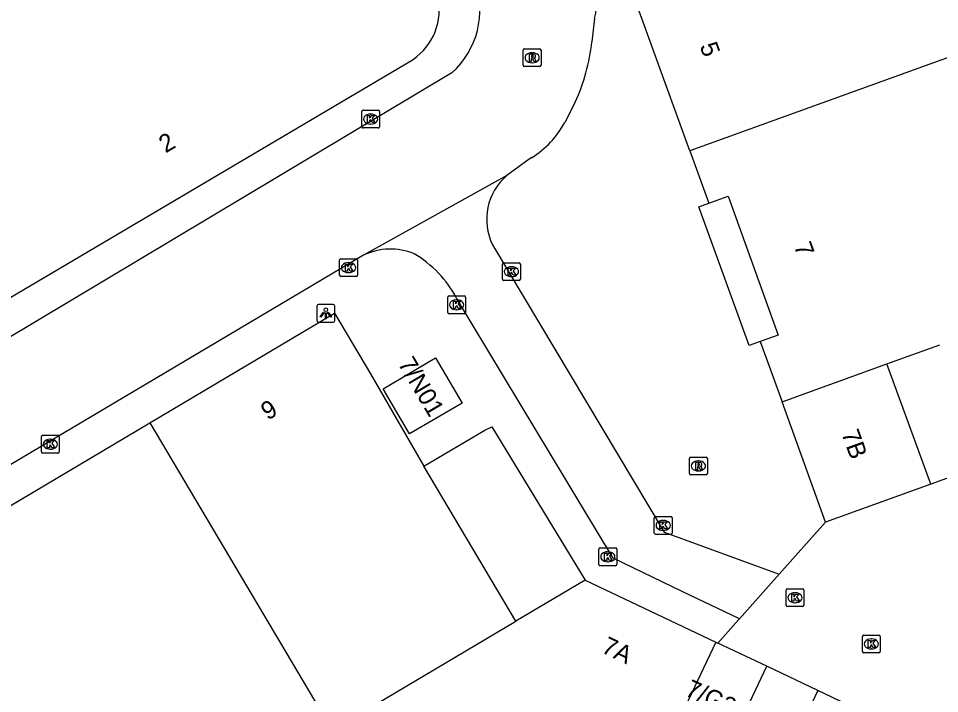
# Model space of a CAD drawing. Extents: x 159503 to 160347, y 382525 to 383272.
# Drawn here: x 159699.9 to 159751.6, y 383023.8 to 383061.7 of the extents above; entities that cross this region are included whole.
import ezdxf

# ---------------------------------------------------------------- set-up
doc = ezdxf.new("R2010")
doc.units = 0
for name, color, linetype in [('IMGEO_Kolk', 7, 'Continuous'), ('IMGEO_Lichtpunt', 7, 'Continuous'), ('IMGEO_Pand', 7, 'Continuous'), ('IMGEO_Pand_nummerreeks', 7, 'Continuous'), ('IMGEO_Rijbaan_lokaal_open', 7, 'Continuous'), ('IMGEO_Rioolput', 7, 'Continuous'), ('IMGEO_Voetpad_open', 7, 'Continuous')]:
    doc.layers.add(name, color=color, linetype=linetype)

msp = doc.modelspace()

# ---------------------------------------------------------------- linework, layer by layer
at = {"layer": 'IMGEO_Kolk'}
for p, q in [((159719.135, 383055.643), (159719.135, 383056.495)), ((159719.21, 383056.569), (159720.062, 383056.569)), ((159720.136, 383056.495), (159720.136, 383055.643)), ((159719.623, 383056.349), (159719.648, 383056.349)), ((159720.062, 383055.569), (159719.21, 383055.569)), ((159719.646, 383055.789), (159719.621, 383055.789)), ((159717.898, 383047.304), (159717.898, 383048.156)), ((159717.973, 383048.23), (159718.825, 383048.23)), ((159718.899, 383048.156), (159718.899, 383047.304)), ((159718.386, 383048.01), (159718.411, 383048.01)), ((159727.046, 383047.074), (159727.046, 383047.926)), ((159727.121, 383048), (159727.973, 383048)), ((159727.534, 383047.78), (159727.559, 383047.78)), ((159728.047, 383047.926), (159728.047, 383047.074)), ((159718.825, 383047.23), (159717.973, 383047.23)), ((159718.409, 383047.45), (159718.384, 383047.45)), ((159727.557, 383047.22), (159727.532, 383047.22)), ((159727.973, 383047), (159727.121, 383047)), ((159723.969, 383045.212), (159723.969, 383046.064)), ((159724.044, 383046.138), (159724.896, 383046.138)), ((159724.97, 383046.064), (159724.97, 383045.212)), ((159724.457, 383045.918), (159724.482, 383045.918)), ((159724.896, 383045.138), (159724.044, 383045.138)), ((159724.48, 383045.358), (159724.455, 383045.358)), ((159701.226, 383038.312), (159702.078, 383038.312)), ((159701.151, 383037.386), (159701.151, 383038.238)), ((159701.639, 383038.092), (159701.664, 383038.092)), ((159702.152, 383038.238), (159702.152, 383037.386)), ((159702.078, 383037.312), (159701.226, 383037.312)), ((159701.662, 383037.532), (159701.637, 383037.532)), ((159735.567, 383032.824), (159735.567, 383033.676)), ((159735.642, 383033.75), (159736.494, 383033.75)), ((159736.568, 383033.676), (159736.568, 383032.824)), ((159736.055, 383033.53), (159736.08, 383033.53)), ((159736.494, 383032.75), (159735.642, 383032.75)), ((159736.078, 383032.97), (159736.053, 383032.97)), ((159732.458, 383031.062), (159732.458, 383031.914)), ((159732.533, 383031.988), (159733.385, 383031.988)), ((159732.946, 383031.768), (159732.971, 383031.768)), ((159733.459, 383031.914), (159733.459, 383031.062)), ((159732.969, 383031.208), (159732.944, 383031.208)), ((159733.385, 383030.988), (159732.533, 383030.988)), ((159742.969, 383028.766), (159742.969, 383029.618)), ((159743.044, 383029.692), (159743.896, 383029.692)), ((159743.457, 383029.472), (159743.482, 383029.472)), ((159743.97, 383029.618), (159743.97, 383028.766)), ((159743.896, 383028.692), (159743.044, 383028.692)), ((159743.48, 383028.912), (159743.455, 383028.912)), ((159747.257, 383026.17), (159747.257, 383027.022)), ((159747.332, 383027.096), (159748.184, 383027.096)), ((159747.745, 383026.876), (159747.77, 383026.876)), ((159748.258, 383027.022), (159748.258, 383026.17)), ((159748.184, 383026.096), (159747.332, 383026.096)), ((159747.768, 383026.316), (159747.743, 383026.316))]:
    msp.add_line(p, q, dxfattribs=at)
for points in [[(159719.135, 383055.643), (159719.135, 383056.495)], [(159719.21, 383056.569), (159720.062, 383056.569)], [(159720.136, 383056.495), (159720.136, 383055.643)], [(159719.456, 383056.269), (159719.579, 383056.269), (159719.579, 383056.118), (159719.709, 383056.269), (159719.873, 383056.269), (159719.727, 383056.118), (159719.88, 383055.869), (159719.728, 383055.869), (159719.643, 383056.033), (159719.579, 383055.966), (159719.579, 383055.869), (159719.456, 383055.869), (159719.456, 383056.269)], [(159720.062, 383055.569), (159719.21, 383055.569)], [(159717.898, 383047.304), (159717.898, 383048.156)], [(159717.973, 383048.23), (159718.825, 383048.23)], [(159718.899, 383048.156), (159718.899, 383047.304)], [(159718.219, 383047.93), (159718.342, 383047.93), (159718.342, 383047.779), (159718.472, 383047.93), (159718.636, 383047.93), (159718.49, 383047.779), (159718.643, 383047.53), (159718.491, 383047.53), (159718.406, 383047.694), (159718.342, 383047.627), (159718.342, 383047.53), (159718.219, 383047.53), (159718.219, 383047.93)], [(159727.046, 383047.074), (159727.046, 383047.926)], [(159727.121, 383048), (159727.973, 383048)], [(159727.367, 383047.7), (159727.49, 383047.7), (159727.49, 383047.549), (159727.62, 383047.7), (159727.784, 383047.7), (159727.638, 383047.549), (159727.791, 383047.3), (159727.639, 383047.3), (159727.554, 383047.464), (159727.49, 383047.397), (159727.49, 383047.3), (159727.367, 383047.3), (159727.367, 383047.7)], [(159728.047, 383047.926), (159728.047, 383047.074)], [(159718.825, 383047.23), (159717.973, 383047.23)], [(159727.973, 383047), (159727.121, 383047)], [(159723.969, 383045.212), (159723.969, 383046.064)], [(159724.044, 383046.138), (159724.896, 383046.138)], [(159724.97, 383046.064), (159724.97, 383045.212)], [(159724.29, 383045.838), (159724.413, 383045.838), (159724.413, 383045.687), (159724.543, 383045.838), (159724.707, 383045.838), (159724.561, 383045.687), (159724.714, 383045.438), (159724.562, 383045.438), (159724.477, 383045.602), (159724.413, 383045.535), (159724.413, 383045.438), (159724.29, 383045.438), (159724.29, 383045.838)], [(159724.896, 383045.138), (159724.044, 383045.138)], [(159701.226, 383038.312), (159702.078, 383038.312)], [(159701.151, 383037.386), (159701.151, 383038.238)], [(159701.472, 383038.012), (159701.595, 383038.012), (159701.595, 383037.861), (159701.725, 383038.012), (159701.889, 383038.012), (159701.743, 383037.861), (159701.896, 383037.612), (159701.744, 383037.612), (159701.659, 383037.776), (159701.595, 383037.709), (159701.595, 383037.612), (159701.472, 383037.612), (159701.472, 383038.012)], [(159702.152, 383038.238), (159702.152, 383037.386)], [(159702.078, 383037.312), (159701.226, 383037.312)], [(159735.567, 383032.824), (159735.567, 383033.676)], [(159735.642, 383033.75), (159736.494, 383033.75)], [(159736.568, 383033.676), (159736.568, 383032.824)], [(159735.888, 383033.45), (159736.011, 383033.45), (159736.011, 383033.299), (159736.141, 383033.45), (159736.305, 383033.45), (159736.159, 383033.299), (159736.312, 383033.05), (159736.16, 383033.05), (159736.075, 383033.214), (159736.011, 383033.147), (159736.011, 383033.05), (159735.888, 383033.05), (159735.888, 383033.45)], [(159736.494, 383032.75), (159735.642, 383032.75)], [(159732.458, 383031.062), (159732.458, 383031.914)], [(159732.533, 383031.988), (159733.385, 383031.988)], [(159732.779, 383031.688), (159732.902, 383031.688), (159732.902, 383031.537), (159733.032, 383031.688), (159733.196, 383031.688), (159733.05, 383031.537), (159733.203, 383031.288), (159733.051, 383031.288), (159732.966, 383031.452), (159732.902, 383031.385), (159732.902, 383031.288), (159732.779, 383031.288), (159732.779, 383031.688)], [(159733.459, 383031.914), (159733.459, 383031.062)], [(159733.385, 383030.988), (159732.533, 383030.988)], [(159742.969, 383028.766), (159742.969, 383029.618)], [(159743.044, 383029.692), (159743.896, 383029.692)], [(159743.97, 383029.618), (159743.97, 383028.766)], [(159743.29, 383029.392), (159743.413, 383029.392), (159743.413, 383029.241), (159743.543, 383029.392), (159743.707, 383029.392), (159743.561, 383029.241), (159743.714, 383028.992), (159743.562, 383028.992), (159743.477, 383029.156), (159743.413, 383029.089), (159743.413, 383028.992), (159743.29, 383028.992), (159743.29, 383029.392)], [(159743.896, 383028.692), (159743.044, 383028.692)], [(159747.257, 383026.17), (159747.257, 383027.022)], [(159747.332, 383027.096), (159748.184, 383027.096)], [(159748.258, 383027.022), (159748.258, 383026.17)], [(159747.578, 383026.796), (159747.701, 383026.796), (159747.701, 383026.645), (159747.831, 383026.796), (159747.995, 383026.796), (159747.849, 383026.645), (159748.002, 383026.396), (159747.85, 383026.396), (159747.765, 383026.56), (159747.701, 383026.493), (159747.701, 383026.396), (159747.578, 383026.396), (159747.578, 383026.796)], [(159748.184, 383026.096), (159747.332, 383026.096)]]:
    msp.add_lwpolyline(points, dxfattribs=at)
for centre, start, end in [((159719.212, 383056.493), 91.552, 178.448), ((159719.212, 383056.493), 91.552, 178.448), ((159720.06, 383056.493), 1.552, 88.448), ((159720.06, 383056.493), 1.552, 88.448), ((159719.212, 383055.645), 181.552, 268.448), ((159719.212, 383055.645), 181.552, 268.448), ((159720.06, 383055.645), 271.552, 358.448), ((159720.06, 383055.645), 271.552, 358.448), ((159717.975, 383048.154), 91.552, 178.448), ((159717.975, 383048.154), 91.552, 178.448), ((159718.823, 383048.154), 1.552, 88.448), ((159718.823, 383048.154), 1.552, 88.448), ((159727.123, 383047.924), 91.552, 178.448), ((159727.123, 383047.924), 91.552, 178.448), ((159727.971, 383047.924), 1.552, 88.448), ((159727.971, 383047.924), 1.552, 88.448), ((159717.975, 383047.306), 181.552, 268.448), ((159717.975, 383047.306), 181.552, 268.448), ((159718.823, 383047.306), 271.552, 358.448), ((159718.823, 383047.306), 271.552, 358.448), ((159727.123, 383047.076), 181.552, 268.448), ((159727.123, 383047.076), 181.552, 268.448), ((159727.971, 383047.076), 271.552, 358.448), ((159727.971, 383047.076), 271.552, 358.448), ((159724.046, 383046.062), 91.552, 178.448), ((159724.046, 383046.062), 91.552, 178.448), ((159724.894, 383046.062), 1.552, 88.448), ((159724.894, 383046.062), 1.552, 88.448), ((159724.046, 383045.214), 181.552, 268.448), ((159724.046, 383045.214), 181.552, 268.448), ((159724.894, 383045.214), 271.552, 358.448), ((159724.894, 383045.214), 271.552, 358.448), ((159701.228, 383038.236), 91.552, 178.448), ((159701.228, 383038.236), 91.552, 178.448), ((159702.076, 383038.236), 1.552, 88.448), ((159702.076, 383038.236), 1.552, 88.448), ((159701.228, 383037.388), 181.552, 268.448), ((159701.228, 383037.388), 181.552, 268.448), ((159702.076, 383037.388), 271.552, 358.448), ((159702.076, 383037.388), 271.552, 358.448), ((159735.644, 383033.674), 91.552, 178.448), ((159735.644, 383033.674), 91.552, 178.448), ((159736.492, 383033.674), 1.552, 88.448), ((159736.492, 383033.674), 1.552, 88.448), ((159735.644, 383032.826), 181.552, 268.448), ((159735.644, 383032.826), 181.552, 268.448), ((159736.492, 383032.826), 271.552, 358.448), ((159736.492, 383032.826), 271.552, 358.448), ((159732.535, 383031.912), 91.552, 178.448), ((159732.535, 383031.912), 91.552, 178.448), ((159733.383, 383031.912), 1.552, 88.448), ((159733.383, 383031.912), 1.552, 88.448), ((159732.535, 383031.064), 181.552, 268.448), ((159732.535, 383031.064), 181.552, 268.448), ((159733.383, 383031.064), 271.552, 358.448), ((159733.383, 383031.064), 271.552, 358.448), ((159743.046, 383029.616), 91.552, 178.448), ((159743.046, 383029.616), 91.552, 178.448), ((159743.894, 383029.616), 1.552, 88.448), ((159743.894, 383029.616), 1.552, 88.448), ((159743.046, 383028.768), 181.552, 268.448), ((159743.046, 383028.768), 181.552, 268.448), ((159743.894, 383028.768), 271.552, 358.448), ((159743.894, 383028.768), 271.552, 358.448), ((159747.334, 383027.02), 91.552, 178.448), ((159747.334, 383027.02), 91.552, 178.448), ((159748.182, 383027.02), 1.552, 88.448), ((159748.182, 383027.02), 1.552, 88.448), ((159747.334, 383026.172), 181.552, 268.448), ((159747.334, 383026.172), 181.552, 268.448), ((159748.182, 383026.172), 271.552, 358.448), ((159748.182, 383026.172), 271.552, 358.448)]:
    msp.add_arc(centre, 0.0765, start, end, dxfattribs=at)
for centre, major_axis, ratio, start_param, end_param in [((159719.622, 383056.069), (-0.387, 0.002), 0.722429, 4.712389, 7.853982), ((159719.647, 383056.069), (-0.39, 0.002), 0.717154, 1.570796, 4.712389), ((159718.385, 383047.73), (-0.387, 0.002), 0.722429, 4.712389, 7.853982), ((159718.41, 383047.73), (-0.39, 0.002), 0.717154, 1.570796, 4.712389), ((159727.533, 383047.5), (-0.387, 0.002), 0.722429, 4.712389, 7.853982), ((159727.558, 383047.5), (-0.39, 0.002), 0.717154, 1.570796, 4.712389), ((159724.456, 383045.638), (-0.387, 0.002), 0.722429, 4.712389, 7.853982), ((159724.481, 383045.638), (-0.39, 0.002), 0.717154, 1.570796, 4.712389), ((159701.638, 383037.812), (-0.387, 0.002), 0.722429, 4.712389, 7.853982), ((159701.663, 383037.812), (-0.39, 0.002), 0.717154, 1.570796, 4.712389), ((159736.054, 383033.25), (-0.387, 0.002), 0.722429, 4.712389, 7.853982), ((159736.079, 383033.25), (-0.39, 0.002), 0.717154, 1.570796, 4.712389), ((159732.945, 383031.488), (-0.387, 0.002), 0.722429, 4.712389, 7.853982), ((159732.97, 383031.488), (-0.39, 0.002), 0.717154, 1.570796, 4.712389), ((159743.456, 383029.192), (-0.387, 0.002), 0.722429, 4.712389, 7.853982), ((159743.481, 383029.192), (-0.39, 0.002), 0.717154, 1.570796, 4.712389), ((159747.744, 383026.596), (-0.387, 0.002), 0.722429, 4.712389, 7.853982), ((159747.769, 383026.596), (-0.39, 0.002), 0.717154, 1.570796, 4.712389)]:
    msp.add_ellipse(centre, major_axis=major_axis, ratio=ratio, start_param=start_param, end_param=end_param, dxfattribs=at)
at = {"layer": 'IMGEO_Lichtpunt'}
for p, q in [((159716.625, 383045.564), (159716.625, 383044.757)), ((159716.625, 383045.564), (159716.625, 383044.757)), ((159717.527, 383045.659), (159716.719, 383045.659)), ((159717.527, 383045.659), (159716.719, 383045.659)), ((159717.621, 383044.757), (159717.621, 383045.564)), ((159717.621, 383044.757), (159717.621, 383045.564)), ((159716.719, 383044.663), (159717.527, 383044.663)), ((159716.719, 383044.663), (159717.527, 383044.663))]:
    msp.add_line(p, q, dxfattribs=at)
for points in [[(159716.999, 383045.228), (159717.038, 383045.2), (159716.85, 383044.938), (159716.812, 383044.965), (159716.999, 383045.228)], [(159717.101, 383045.18), (159717.148, 383045.18), (159717.148, 383044.858), (159717.101, 383044.858), (159717.101, 383045.18)], [(159717.211, 383045.2), (159717.249, 383045.227), (159717.436, 383044.965), (159717.397, 383044.937), (159717.211, 383045.2)]]:
    msp.add_lwpolyline(points, dxfattribs=at)
msp.add_circle((159717.124, 383045.362), 0.0994, dxfattribs=at)
for centre, start, end in [((159716.719, 383045.564), 90, 180), ((159716.719, 383045.564), 90, 180), ((159717.527, 383045.564), 0, 90), ((159717.527, 383045.564), 0, 90), ((159716.719, 383044.757), 180, 270), ((159716.719, 383044.757), 180, 270), ((159717.527, 383044.757), 270, 0), ((159717.527, 383044.757), 270, 360)]:
    msp.add_arc(centre, 0.0946, start, end, dxfattribs=at)
at = {"layer": 'IMGEO_Pand'}
for points in [[(159737.559, 383054.283), (159734.103, 383063.845)], [(159763.853, 383063.79), (159737.559, 383054.283)], [(159697.266, 383044.792), (159722.024, 383059.424)], [(159737.559, 383054.283), (159738.623, 383051.341)], [(159738.623, 383051.341), (159739.709, 383051.733), (159742.526, 383043.943), (159741.521, 383043.58)], [(159707.235, 383039.014), (159717.603, 383045.17), (159719.625, 383041.765), (159722.634, 383036.573)], [(159741.521, 383043.58), (159742.744, 383040.198)], [(159748.633, 383042.324), (159748.835, 383042.397), (159751.595, 383043.394)], [(159723.282, 383042.66), (159724.785, 383040.12), (159721.813, 383038.389), (159720.341, 383040.928), (159723.282, 383042.66)], [(159742.744, 383040.198), (159745.695, 383041.263), (159748.633, 383042.324)], [(159751.091, 383035.561), (159748.633, 383042.324)], [(159745.192, 383033.428), (159742.744, 383040.198)], [(159681.512, 383023.741), (159707.235, 383039.014)], [(159707.235, 383039.014), (159717.447, 383021.814)], [(159727.798, 383027.878), (159722.634, 383036.573)], [(159754.041, 383036.627), (159751.091, 383035.561)], [(159751.091, 383035.561), (159748.141, 383034.494), (159745.192, 383033.428)], [(159731.677, 383030.181), (159727.798, 383027.878)], [(159731.677, 383030.181), (159739.021, 383026.698)], [(159719.37, 383022.877), (159727.798, 383027.878)], [(159739.021, 383026.698), (159736.443, 383021.244)], [(159739.021, 383026.698), (159739.133, 383026.645)], [(159741.889, 383025.338), (159739.133, 383026.645)], [(159739.304, 383019.887), (159741.889, 383025.338)], [(159744.757, 383023.978), (159741.889, 383025.338)], [(159744.757, 383023.978), (159742.172, 383018.527)], [(159747.624, 383022.618), (159744.757, 383023.978)]]:
    msp.add_lwpolyline(points, dxfattribs=at)
msp.add_arc((159720.134, 383062.196), 3.356, 304.2878, 13.0138, dxfattribs=at)
at = {"layer": 'IMGEO_Rijbaan_lokaal_open'}
for points in [[(159732.21, 383061.722), (159732.068, 383060.401)], [(159724.205, 383058.665), (159687.242, 383036.582), (159585.591, 382976.257)], [(159731.133, 383057.017), (159730.536, 383055.877)], [(159728.679, 383053.903), (159727.295, 383052.907)], [(159727.295, 383052.907), (159719.236, 383048.422)], [(159726.49, 383049.005), (159736.117, 383032.871), (159742.586, 383030.512)], [(159719.236, 383048.422), (159586.71, 382969.778)], [(159740.345, 383028.003), (159737.168, 383029.529), (159733.254, 383031.409), (159724.468, 383046.005)], [(159740.345, 383028.003), (159742.586, 383030.512)]]:
    msp.add_lwpolyline(points, dxfattribs=at)
for centre, radius, start, end in [((159721.044, 383062.184), 4.73, 311.9285, 20.0777), ((159729.181, 383062.54), 3.138, 344.8895, 29.7111), ((159720.774, 383061.7), 11.369, 335.6722, 353.4368), ((159725.929, 383058.35), 5.229, 301.7291, 331.7695), ((159729.391, 383050.441), 3.236, 130.3532, 206.3331), ((159720.753, 383045.275), 3.493, 67.6806, 115.7432), ((159718.836, 383043.02), 6.374, 27.9229, 59.4062)]:
    msp.add_arc(centre, radius, start, end, dxfattribs=at)
at = {"layer": 'IMGEO_Rioolput'}
for p, q in [((159728.283, 383060.016), (159729.135, 383060.016)), ((159728.208, 383059.09), (159728.208, 383059.942)), ((159728.696, 383059.796), (159728.721, 383059.796)), ((159729.209, 383059.942), (159729.209, 383059.09)), ((159729.135, 383059.016), (159728.283, 383059.016)), ((159728.719, 383059.236), (159728.694, 383059.236)), ((159737.546, 383036.166), (159737.546, 383037.018)), ((159737.621, 383037.092), (159738.473, 383037.092)), ((159738.034, 383036.872), (159738.059, 383036.872)), ((159738.547, 383037.018), (159738.547, 383036.166)), ((159738.057, 383036.312), (159738.032, 383036.312)), ((159738.473, 383036.092), (159737.621, 383036.092))]:
    msp.add_line(p, q, dxfattribs=at)
for points in [[(159728.283, 383060.016), (159729.135, 383060.016)], [(159728.208, 383059.09), (159728.208, 383059.942)], [(159728.797, 383059.714), (159728.545, 383059.716), (159728.545, 383059.316)], [(159728.545, 383059.316), (159728.669, 383059.316), (159728.669, 383059.478), (159728.68, 383059.478)], [(159728.723, 383059.635), (159728.669, 383059.635), (159728.669, 383059.554)], [(159728.669, 383059.554), (159728.721, 383059.554)], [(159729.209, 383059.942), (159729.209, 383059.09)], [(159729.135, 383059.016), (159728.283, 383059.016)], [(159728.727, 383059.449), (159728.798, 383059.316), (159728.938, 383059.316), (159728.873, 383059.442)], [(159737.546, 383036.166), (159737.546, 383037.018)], [(159737.621, 383037.092), (159738.473, 383037.092)], [(159738.135, 383036.79), (159737.883, 383036.792), (159737.883, 383036.392)], [(159738.061, 383036.711), (159738.007, 383036.711), (159738.007, 383036.63)], [(159738.547, 383037.018), (159738.547, 383036.166)], [(159737.883, 383036.392), (159738.007, 383036.392), (159738.007, 383036.554), (159738.018, 383036.554)], [(159738.007, 383036.63), (159738.059, 383036.63)], [(159738.065, 383036.525), (159738.136, 383036.392), (159738.276, 383036.392), (159738.211, 383036.518)], [(159738.473, 383036.092), (159737.621, 383036.092)]]:
    msp.add_lwpolyline(points, dxfattribs=at)
for centre, radius, start, end in [((159728.285, 383059.94), 0.0765, 91.552, 178.448), ((159728.285, 383059.94), 0.0765, 91.552, 178.448), ((159729.133, 383059.94), 0.0765, 1.552, 88.448), ((159729.133, 383059.94), 0.0765, 1.552, 88.448), ((159728.679, 383059.425), 0.0533, 26.0293, 88.6989), ((159728.705, 383059.743), 0.19, 274.7715, 282.9687), ((159728.729, 383059.539), 0.0964, 77.0061, 93.1865), ((159728.743, 383059.596), 0.0378, 276.6634, 79.6772), ((159728.796, 383059.604), 0.109, 350.3612, 89.416), ((159728.794, 383059.604), 0.112, 277.5842, 350.9817), ((159728.778, 383059.389), 0.108, 29.5134, 73.7905), ((159728.285, 383059.092), 0.0765, 181.552, 268.448), ((159728.285, 383059.092), 0.0765, 181.552, 268.448), ((159729.133, 383059.092), 0.0765, 271.552, 358.448), ((159729.133, 383059.092), 0.0765, 271.552, 358.448), ((159737.623, 383037.016), 0.0765, 91.552, 178.448), ((159737.623, 383037.016), 0.0765, 91.552, 178.448), ((159738.067, 383036.615), 0.0964, 77.0061, 93.1865), ((159738.081, 383036.672), 0.0378, 276.6634, 79.6772), ((159738.134, 383036.68), 0.109, 350.3612, 89.416), ((159738.471, 383037.016), 0.0765, 1.552, 88.448), ((159738.471, 383037.016), 0.0765, 1.552, 88.448), ((159738.017, 383036.501), 0.0533, 26.0293, 88.6989), ((159738.043, 383036.819), 0.19, 274.7715, 282.9687), ((159738.132, 383036.68), 0.112, 277.5842, 350.9817), ((159738.116, 383036.465), 0.108, 29.5134, 73.7905), ((159737.623, 383036.168), 0.0765, 181.552, 268.448), ((159737.623, 383036.168), 0.0765, 181.552, 268.448), ((159738.471, 383036.168), 0.0765, 271.552, 358.448), ((159738.471, 383036.168), 0.0765, 271.552, 358.448)]:
    msp.add_arc(centre, radius, start, end, dxfattribs=at)
for centre, major_axis, ratio, start_param, end_param in [((159728.695, 383059.516), (-0.387, 0.002), 0.722429, 4.712389, 7.853982), ((159728.72, 383059.516), (-0.39, 0.002), 0.717154, 1.570796, 4.712389), ((159738.033, 383036.592), (-0.387, 0.002), 0.722429, 4.712389, 7.853982), ((159738.058, 383036.592), (-0.39, 0.002), 0.717154, 1.570796, 4.712389)]:
    msp.add_ellipse(centre, major_axis=major_axis, ratio=ratio, start_param=start_param, end_param=end_param, dxfattribs=at)
at = {"layer": 'IMGEO_Voetpad_open'}
for points in [[(159741.521, 383043.58), (159740.89, 383043.351), (159738.063, 383051.137), (159738.623, 383051.341)], [(159722.634, 383036.573), (159726.061, 383038.608), (159726.443, 383038.795), (159731.677, 383030.181)], [(159742.586, 383030.512), (159745.192, 383033.428)], [(159739.133, 383026.645), (159740.305, 383027.958), (159740.345, 383028.003)]]:
    msp.add_lwpolyline(points, dxfattribs=at)

# ---------------------------------------------------------------- texts
at = {"layer": 'IMGEO_Pand_nummerreeks'}
for s, rotation, p in [('5', 289.8714, (159738.107, 383060.18)), ('2', 30.5831, (159708.125, 383054.137)), ('7', 289.8814, (159743.393, 383048.953)), ('7/N01', 300.6129, (159721.147, 383042.339)), ('9', 30.6997, (159713.858, 383039.131)), ('7B', 289.8798, (159746.064, 383038.427)), ('7A', 334.6294, (159732.538, 383026.143)), ('7/G21', 335.7541, (159737.235, 383023.725))]:
    msp.add_text(s, height=1, rotation=rotation, dxfattribs=at).set_placement(p)

doc.saveas('drawing.dxf')
